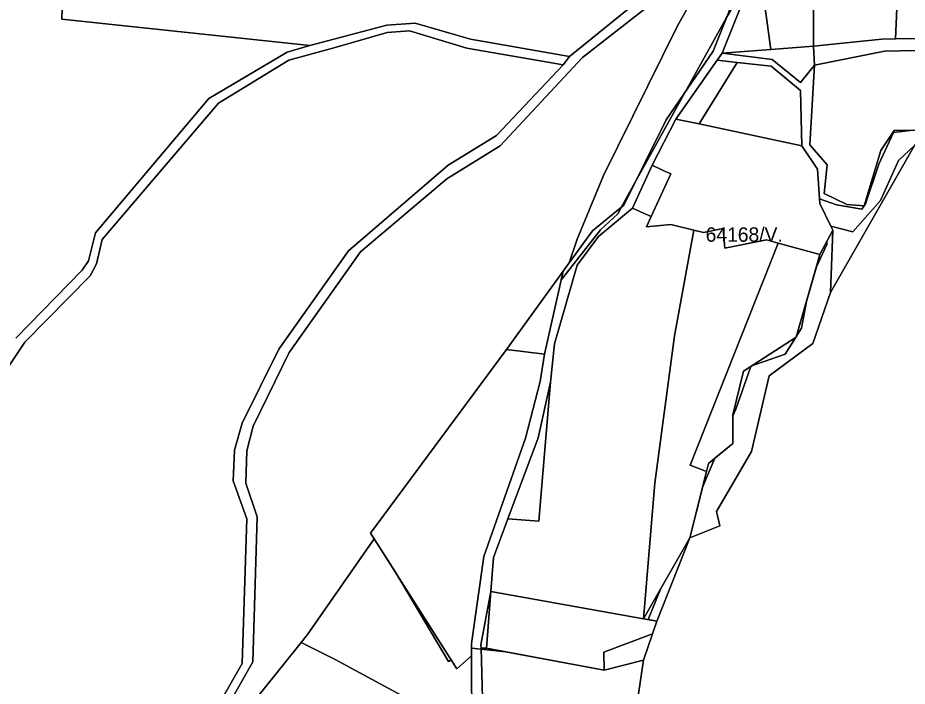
# Model space of a CAD drawing. Extents: x -502026 to -497664, y -1143484 to -1138019.
# Drawn here: x -499334 to -498840.3, y -1142180.2 to -1141809.3 of the extents above; entities that cross this region are included whole.
import ezdxf

# ---------------------------------------------------------------- set-up
doc = ezdxf.new("R2010")
doc.units = 0
for name, color, linetype in [('25', 7, 'Continuous'), ('37', 7, 'Continuous'), ('43', 7, 'Continuous'), ('55', 7, 'Continuous'), ('62', 7, 'Continuous')]:
    doc.layers.add(name, color=color, linetype=linetype)

msp = doc.modelspace()

# ---------------------------------------------------------------- linework, layer by layer
at = {"layer": '25'}
for points in [[(-498910.48, -1141760.98), (-498913.85, -1141780.13), (-498916.09, -1141785.79), (-498919.9, -1141798.31), (-498915.99, -1141826.84), (-498943.06, -1141828.91), (-498925.67, -1141785.22), (-498922.29, -1141773.68), (-498920.46, -1141756.88)], [(-498892.36, -1141797), (-498892.39, -1141825.03), (-498915.99, -1141826.84), (-498919.9, -1141798.31), (-498916.09, -1141785.79), (-498913.85, -1141780.13), (-498915.15, -1141787.55), (-498906.17, -1141796.31)], [(-498891.75, -1141835.55), (-498899.63, -1141845.2), (-498915.22, -1141832.49), (-498943.06, -1141828.91), (-498915.99, -1141826.84), (-498892.39, -1141825.03)], [(-498955.87, -1141868.21), (-498898.82, -1141880.4), (-498890.08, -1141893.23), (-498888.84, -1141912.29), (-498882.72, -1141924.83), (-498881.6, -1141927.22), (-498888.78, -1141940.6), (-498911.92, -1141934.31), (-498918.39, -1141932.55), (-498941.47, -1141937.19), (-498942.56, -1141926.3), (-498953.36, -1141928.4), (-498958.77, -1141927.1), (-498971.56, -1141924.04), (-498985.09, -1141925.35), (-498982.45, -1141919.58), (-498971.61, -1141895.86), (-498975.81, -1141893.93), (-498981.9, -1141891.14), (-498968.75, -1141865.46)]]:
    msp.add_lwpolyline(points, close=True, dxfattribs=at)
at = {"layer": '37'}
for points in [[(-498846.81, -1141820.95), (-498854.34, -1141821.04), (-498892.39, -1141825.03), (-498892.36, -1141797), (-498886.83, -1141797.28), (-498886.41, -1141788.85), (-498877.82, -1141789.19), (-498877.22, -1141774.18), (-498885.71, -1141773.84), (-498885.43, -1141769.27), (-498884.13, -1141769.34), (-498883.76, -1141762.05), (-498890.85, -1141761.69), (-498890.21, -1141752.47), (-498844.38, -1141766.25)], [(-498934.78, -1141833.99), (-498955.87, -1141868.21), (-498968.75, -1141865.46), (-498945.8, -1141832.8)], [(-498898.82, -1141880.4), (-498955.87, -1141868.21), (-498934.78, -1141833.99), (-498915.86, -1141836.03), (-498899.63, -1141849.7)], [(-498982.45, -1141919.58), (-498985.09, -1141925.35), (-498971.56, -1141924.04), (-498958.77, -1141927.1), (-498969.54, -1141985.75), (-498980.35, -1142067.49), (-498986.68, -1142142.79), (-499071.46, -1142127.74), (-499070.05, -1142108.88), (-499062.01, -1142087.44), (-499044.78, -1142088.72), (-499038.36, -1142011.47), (-499036.18, -1141990.24), (-499023.43, -1141946.54), (-499011.61, -1141930.58), (-498992.79, -1141914.86), (-498986.65, -1141917.66)], [(-498911.92, -1141934.31), (-498960.87, -1142057.51), (-498951.7, -1142061.13), (-498960.97, -1142097.88), (-498986.68, -1142142.79), (-498980.35, -1142067.49), (-498969.54, -1141985.75), (-498958.77, -1141927.1), (-498953.36, -1141928.4), (-498942.56, -1141926.3), (-498941.47, -1141937.19), (-498918.39, -1141932.55)], [(-498888.78, -1141940.6), (-498901.96, -1141986.59), (-498931.12, -1142005.42), (-498937.03, -1142029.69), (-498937.19, -1142045.49), (-498950.56, -1142056.61), (-498951.7, -1142061.13), (-498960.87, -1142057.51), (-498911.92, -1141934.31)], [(-499041.57, -1141995.88), (-499062.72, -1141993.39), (-499031.31, -1141949.87)], [(-499041.57, -1141995.88), (-499044.1, -1142011.04), (-499052.19, -1142042.49), (-499075.29, -1142108.31), (-499082.23, -1142156.57), (-499082.18, -1142163.47), (-499090.26, -1142170.56), (-499136.16, -1142098.44), (-499138.16, -1142095.3), (-499062.72, -1141993.39)], [(-499073.82, -1142159.22), (-499076.87, -1142159.22), (-499076.92, -1142157.36), (-499071.46, -1142127.74)], [(-498986.68, -1142142.79), (-498979.27, -1142144.11), (-498981.73, -1142151.22), (-499008.66, -1142161.33), (-499008.54, -1142171.43), (-499073.82, -1142159.22), (-499071.46, -1142127.74)], [(-498986.74, -1142165.73), (-499008.54, -1142171.43), (-499008.66, -1142161.33), (-498981.73, -1142151.22)]]:
    msp.add_lwpolyline(points, close=True, dxfattribs=at)
at = {"layer": '43'}
for points in [[(-499027.92, -1141945.25), (-499023.61, -1141932.15), (-499008.86, -1141896.85), (-498968.07, -1141814.16), (-498950.78, -1141783.19), (-498946.07, -1141767.37), (-498929.98, -1141670.65), (-498921.68, -1141635.2), (-498920.59, -1141634.58), (-498926.5, -1141670.63), (-498931.31, -1141705.25), (-498930.78, -1141784.47), (-498947.98, -1141827.73), (-498974.11, -1141865.96), (-498997.66, -1141913.35), (-499014.95, -1141927.46)], [(-499027.8, -1141830.67), (-499082.65, -1141821.14), (-499113.38, -1141812.34), (-499129.26, -1141813.42), (-499172.01, -1141824.57), (-499309.5, -1141810.04), (-499308.25, -1141766.4), (-499287.57, -1141756.18), (-499249.1, -1141748.32), (-499199.06, -1141737.08), (-499145.06, -1141731.43), (-499129.99, -1141722.36), (-499082.44, -1141707.67), (-499056.59, -1141688.2), (-499031.84, -1141671.1), (-498961.91, -1141670.81), (-498962.33, -1141691.39), (-498959.01, -1141711.02), (-498962.92, -1141751.08), (-498976.71, -1141778.83), (-498987.01, -1141797.69)], [(-498771.05, -1141724.78), (-498783.82, -1141781.52), (-498793.62, -1141789.4), (-498800.65, -1141800.45), (-498815.52, -1141828.19), (-498827.1, -1141820.71), (-498846.81, -1141820.95), (-498844.38, -1141766.25), (-498890.21, -1141752.47), (-498898.8, -1141749.89), (-498892.28, -1141695.09), (-498823.99, -1141707.76), (-498800.16, -1141713.8)], [(-498815.52, -1141828.19), (-498823.56, -1141834.14), (-498835.45, -1141827.39), (-498852.97, -1141827.71), (-498891.75, -1141835.55), (-498892.39, -1141825.03), (-498854.34, -1141821.04), (-498846.81, -1141820.95), (-498827.1, -1141820.71)], [(-498823.56, -1141834.14), (-498831.8, -1141848.82), (-498830.19, -1141858.46), (-498831.43, -1141871.58), (-498847.49, -1141871.9), (-498854.88, -1141882.87), (-498864.27, -1141913.69), (-498873.75, -1141912.84), (-498886.43, -1141906.85), (-498884.68, -1141890.79), (-498894.3, -1141879.79), (-498891.75, -1141835.55), (-498852.97, -1141827.71), (-498835.45, -1141827.39)], [(-498891.75, -1141835.55), (-498894.3, -1141879.79), (-498884.68, -1141890.79), (-498886.43, -1141906.85), (-498873.75, -1141912.84), (-498864.27, -1141913.69), (-498854.88, -1141882.87), (-498847.49, -1141871.9), (-498831.43, -1141871.58), (-498836.29, -1141880.09), (-498845.19, -1141888.54), (-498855.09, -1141910.58), (-498870.57, -1141928.09), (-498882.72, -1141924.83), (-498888.84, -1141912.29), (-498890.08, -1141893.23), (-498898.82, -1141880.4), (-498899.63, -1141849.7), (-498915.86, -1141836.03), (-498934.78, -1141833.99), (-498945.8, -1141832.8), (-498943.06, -1141828.91), (-498915.22, -1141832.49), (-498899.63, -1141845.2)], [(-498882.96, -1141961.82), (-498881.6, -1141927.22), (-498882.72, -1141924.83), (-498870.57, -1141928.09), (-498855.09, -1141910.58), (-498845.19, -1141888.54), (-498836.29, -1141880.09)], [(-498882.96, -1141961.82), (-498892.62, -1141990.07), (-498916.9, -1142007.92), (-498926.81, -1142050.05), (-498946.13, -1142083.27), (-498944.37, -1142091.31), (-498960.97, -1142097.88), (-498951.7, -1142061.13), (-498950.56, -1142056.61), (-498937.19, -1142045.49), (-498937.03, -1142029.69), (-498931.12, -1142005.42), (-498901.96, -1141986.59), (-498888.78, -1141940.6), (-498881.6, -1141927.22)], [(-499154.36, -1142307.73), (-499186.12, -1142301.39), (-499188.68, -1142300.88), (-499186.97, -1142296.09), (-499184.66, -1142289.64), (-499201.29, -1142287.31), (-499213.51, -1142301.06), (-499214.98, -1142319.37), (-499232.07, -1142321.48), (-499232.05, -1142321.31), (-499209.91, -1142197.26), (-499176.7, -1142155.94), (-499157.93, -1142165.39), (-499089.78, -1142202.21), (-499094.44, -1142225.21), (-499115.5, -1142261.23), (-499136.07, -1142276.67), (-499149.25, -1142296.12)], [(-499008.54, -1142171.43), (-498986.74, -1142165.73), (-498995.91, -1142227.94), (-499026.62, -1142323.09), (-499050.24, -1142319.92), (-499062.13, -1142314.94), (-499075.8, -1142301.27), (-499086.08, -1142284.71), (-499093.39, -1142285.2), (-499089.62, -1142275.22), (-499092.51, -1142241.43), (-499075.48, -1142207.66), (-499076.87, -1142159.22), (-499073.82, -1142159.22)]]:
    msp.add_lwpolyline(points, close=True, dxfattribs=at)
for points in [[(-499351.55, -1141781.17), (-499313.61, -1141769.05), (-499308.25, -1141766.4), (-499309.5, -1141810.04), (-499172.01, -1141824.57), (-499184.44, -1141828.26), (-499227.9, -1141853.97), (-499290.94, -1141928.56), (-499294.82, -1141944.23), (-499298.38, -1141949.37), (-499335.18, -1141987.04)], [(-498950.78, -1141783.19), (-498968.07, -1141814.16), (-499008.86, -1141896.85), (-499023.61, -1141932.15), (-499027.92, -1141945.25), (-499031.31, -1141949.87), (-499062.72, -1141993.39), (-499138.16, -1142095.3), (-499136.16, -1142098.44), (-499173.2, -1142151.59), (-499176.7, -1142155.94), (-499209.91, -1142197.26)], [(-499215.45, -1142187.61), (-499203.6, -1142166.74), (-499201.1, -1142086.29), (-499207.37, -1142067.47), (-499206.81, -1142049.7), (-499203.35, -1142035.87), (-499183.34, -1141995.03), (-499143.86, -1141939.16), (-499095.81, -1141898.69), (-499066.33, -1141880.3), (-499020.49, -1141831.23), (-498981.94, -1141801.18)], [(-499371.45, -1142050.9), (-499330.13, -1141989.35), (-499293.77, -1141952.54), (-499290.27, -1141945.8), (-499287.17, -1141932.36), (-499222.56, -1141856.69), (-499183.62, -1141832.74), (-499157.82, -1141825.76), (-499129.04, -1141817.39), (-499116.59, -1141816.42), (-499084.68, -1141826.07), (-499031.33, -1141835.4), (-499068.25, -1141874.53), (-499095.09, -1141891.05), (-499150.37, -1141938.55), (-499189.06, -1141993.13), (-499209.45, -1142034.3), (-499213.75, -1142049.16), (-499214.42, -1142066.21), (-499206.98, -1142087.36), (-499209.55, -1142167.56), (-499220.57, -1142186.98)], [(-498995.91, -1142227.94), (-498986.74, -1142165.73), (-498981.73, -1142151.22), (-498979.27, -1142144.11), (-498979.18, -1142143.85), (-498960.97, -1142097.88), (-498944.37, -1142091.31), (-498946.13, -1142083.27), (-498926.81, -1142050.05), (-498916.9, -1142007.92), (-498892.62, -1141990.07), (-498882.96, -1141961.82), (-498836.29, -1141880.09)], [(-499227.31, -1142507.01), (-499216.16, -1142395.67), (-499212.53, -1142388.21), (-499170.99, -1142395.83), (-499154.36, -1142307.73), (-499149.25, -1142296.12), (-499136.07, -1142276.67), (-499115.5, -1142261.23), (-499094.44, -1142225.21), (-499089.78, -1142202.21), (-499157.93, -1142165.39), (-499176.7, -1142155.94), (-499173.2, -1142151.59), (-499136.16, -1142098.44), (-499090.26, -1142170.56), (-499082.18, -1142163.47), (-499081.91, -1142204.53), (-499096.53, -1142242.64), (-499093.48, -1142273.45), (-499122.89, -1142350.8), (-499130.54, -1142422.37), (-499143.8, -1142472.44), (-499140.33, -1142516.56)]]:
    msp.add_lwpolyline(points, dxfattribs=at)
at = {"layer": '55'}
for points in [[(-499081.91, -1142204.53), (-499082.18, -1142163.47), (-499082.23, -1142156.57), (-499075.29, -1142108.31), (-499052.19, -1142042.49), (-499044.1, -1142011.04), (-499041.57, -1141995.88), (-499031.31, -1141949.87), (-499027.92, -1141945.25), (-499014.95, -1141927.46), (-498997.66, -1141913.35), (-498974.11, -1141865.96), (-498947.98, -1141827.73), (-498930.78, -1141784.47)], [(-498925.67, -1141785.22), (-498943.06, -1141828.91), (-498945.8, -1141832.8), (-498968.75, -1141865.46), (-498981.9, -1141891.14), (-498992.79, -1141914.86), (-499011.61, -1141930.58), (-499023.43, -1141946.54), (-499036.18, -1141990.24), (-499038.36, -1142011.47), (-499045.13, -1142042.4), (-499062.01, -1142087.44), (-499070.05, -1142108.88), (-499071.46, -1142127.74), (-499076.92, -1142157.36), (-499076.87, -1142159.22), (-499075.48, -1142207.66)], [(-499220.57, -1142186.98), (-499209.55, -1142167.56), (-499206.98, -1142087.36), (-499214.42, -1142066.21), (-499213.75, -1142049.16), (-499209.45, -1142034.3), (-499189.06, -1141993.13), (-499150.37, -1141938.55), (-499095.09, -1141891.05), (-499068.25, -1141874.53), (-499031.33, -1141835.4), (-499027.8, -1141830.67), (-498987.01, -1141797.69)], [(-498981.94, -1141801.18), (-499020.49, -1141831.23), (-499066.33, -1141880.3), (-499095.81, -1141898.69), (-499143.86, -1141939.16), (-499183.34, -1141995.03), (-499203.35, -1142035.87), (-499206.81, -1142049.7), (-499207.37, -1142067.47), (-499201.1, -1142086.29), (-499203.6, -1142166.74), (-499215.45, -1142187.61)], [(-499335.18, -1141987.04), (-499298.38, -1141949.37), (-499294.82, -1141944.23), (-499290.94, -1141928.56), (-499227.9, -1141853.97), (-499184.44, -1141828.26), (-499172.01, -1141824.57), (-499129.26, -1141813.42), (-499113.38, -1141812.34), (-499082.65, -1141821.14), (-499027.8, -1141830.67), (-499031.33, -1141835.4), (-499084.68, -1141826.07), (-499116.59, -1141816.42), (-499129.04, -1141817.39), (-499157.82, -1141825.76), (-499183.62, -1141832.74), (-499222.56, -1141856.69), (-499287.17, -1141932.36), (-499290.27, -1141945.8), (-499293.77, -1141952.54), (-499330.13, -1141989.35), (-499371.45, -1142050.9)]]:
    msp.add_lwpolyline(points, dxfattribs=at)
for points in [[(-498982.45, -1141919.58), (-498986.65, -1141917.66), (-498992.79, -1141914.86), (-498981.9, -1141891.14), (-498975.81, -1141893.93), (-498971.61, -1141895.86)], [(-499062.01, -1142087.44), (-499045.13, -1142042.4), (-499038.36, -1142011.47), (-499044.78, -1142088.72)], [(-498979.27, -1142144.11), (-498986.68, -1142142.79), (-498960.97, -1142097.88), (-498979.18, -1142143.85)]]:
    msp.add_lwpolyline(points, close=True, dxfattribs=at)
at = {"layer": '62'}
for points in [[(-498837.24, -1141871.69), (-498848, -1141873), (-498856, -1141890.5), (-498863.5, -1141912.5), (-498864.25, -1141913.62), (-498864.29, -1141913.69), (-498865.5, -1141915.5), (-498879.5, -1141913), (-498889.01, -1141909.69), (-498888.84, -1141912.29), (-498882.72, -1141924.83), (-498881.6, -1141927.22), (-498884.9, -1141933.38), (-498885, -1141935), (-498890.74, -1141947.43), (-498896.26, -1141966.69), (-498899, -1141981.5), (-498901.79, -1141985.99), (-498901.96, -1141986.59), (-498902.29, -1141986.8), (-498908, -1141996), (-498919.69, -1142000), (-498926.15, -1142002.21), (-498927.12, -1142002.84), (-498935.5, -1142026.5), (-498937.03, -1142030.1), (-498937.19, -1142045.49), (-498947.1, -1142053.73), (-498953.81, -1142069.48), (-498960.97, -1142097.88), (-498977.33, -1142126.46), (-498984.2, -1142143.23), (-498979.27, -1142144.11), (-498981.73, -1142151.22), (-498986.74, -1142165.73), (-499008.54, -1142171.43), (-499063.28, -1142161.19), (-499076.86, -1142159.68), (-499082.21, -1142159.09), (-499082.18, -1142163.47), (-499090.26, -1142170.56), (-499093.46, -1142165.54), (-499095, -1142166.5), (-499124.33, -1142117.03), (-499136.16, -1142098.44), (-499138.16, -1142095.3), (-499062.72, -1141993.39), (-499031.31, -1141949.87), (-499032.38, -1141954.65), (-499031.5, -1141953.5), (-499010.5, -1141927), (-499001, -1141918), (-498999.04, -1141914.48), (-498991.24, -1141900.44), (-498963.31, -1141850.16), (-498940.76, -1141809.56), (-498933.5, -1141796.5)], [(-498933.5, -1141796.5), (-498940.76, -1141809.56), (-498963.31, -1141850.16), (-498991.24, -1141900.44), (-498999.04, -1141914.48), (-499001, -1141918), (-499010.5, -1141927), (-499031.5, -1141953.5), (-499032.38, -1141954.65), (-499031.31, -1141949.87), (-499062.72, -1141993.39), (-499138.16, -1142095.3), (-499136.16, -1142098.44), (-499124.33, -1142117.03), (-499095, -1142166.5), (-499093.46, -1142165.54), (-499090.26, -1142170.56), (-499082.18, -1142163.47), (-499082.21, -1142159.09), (-499076.86, -1142159.68), (-499063.28, -1142161.19), (-499008.54, -1142171.43), (-498986.74, -1142165.73), (-498981.73, -1142151.22), (-498979.27, -1142144.11), (-498984.2, -1142143.23), (-498977.33, -1142126.46), (-498960.97, -1142097.88), (-498953.81, -1142069.48), (-498947.1, -1142053.73), (-498937.19, -1142045.49), (-498937.03, -1142030.1), (-498935.5, -1142026.5), (-498927.12, -1142002.84), (-498926.15, -1142002.21), (-498919.69, -1142000), (-498908, -1141996), (-498902.29, -1141986.8), (-498901.96, -1141986.59), (-498901.79, -1141985.99), (-498899, -1141981.5), (-498896.26, -1141966.69), (-498890.74, -1141947.43), (-498885, -1141935), (-498884.9, -1141933.38), (-498881.6, -1141927.22), (-498882.72, -1141924.83), (-498888.84, -1141912.29), (-498889.01, -1141909.69), (-498879.5, -1141913), (-498865.5, -1141915.5), (-498864.29, -1141913.69), (-498864.25, -1141913.62), (-498863.5, -1141912.5), (-498856, -1141890.5), (-498848, -1141873), (-498837.24, -1141871.69)]]:
    msp.add_lwpolyline(points, dxfattribs=at)

# ---------------------------------------------------------------- texts
msp.add_text('64168/V.', height=8, dxfattribs=at).set_placement((-498952.21, -1141933.57))

doc.saveas('drawing.dxf')
